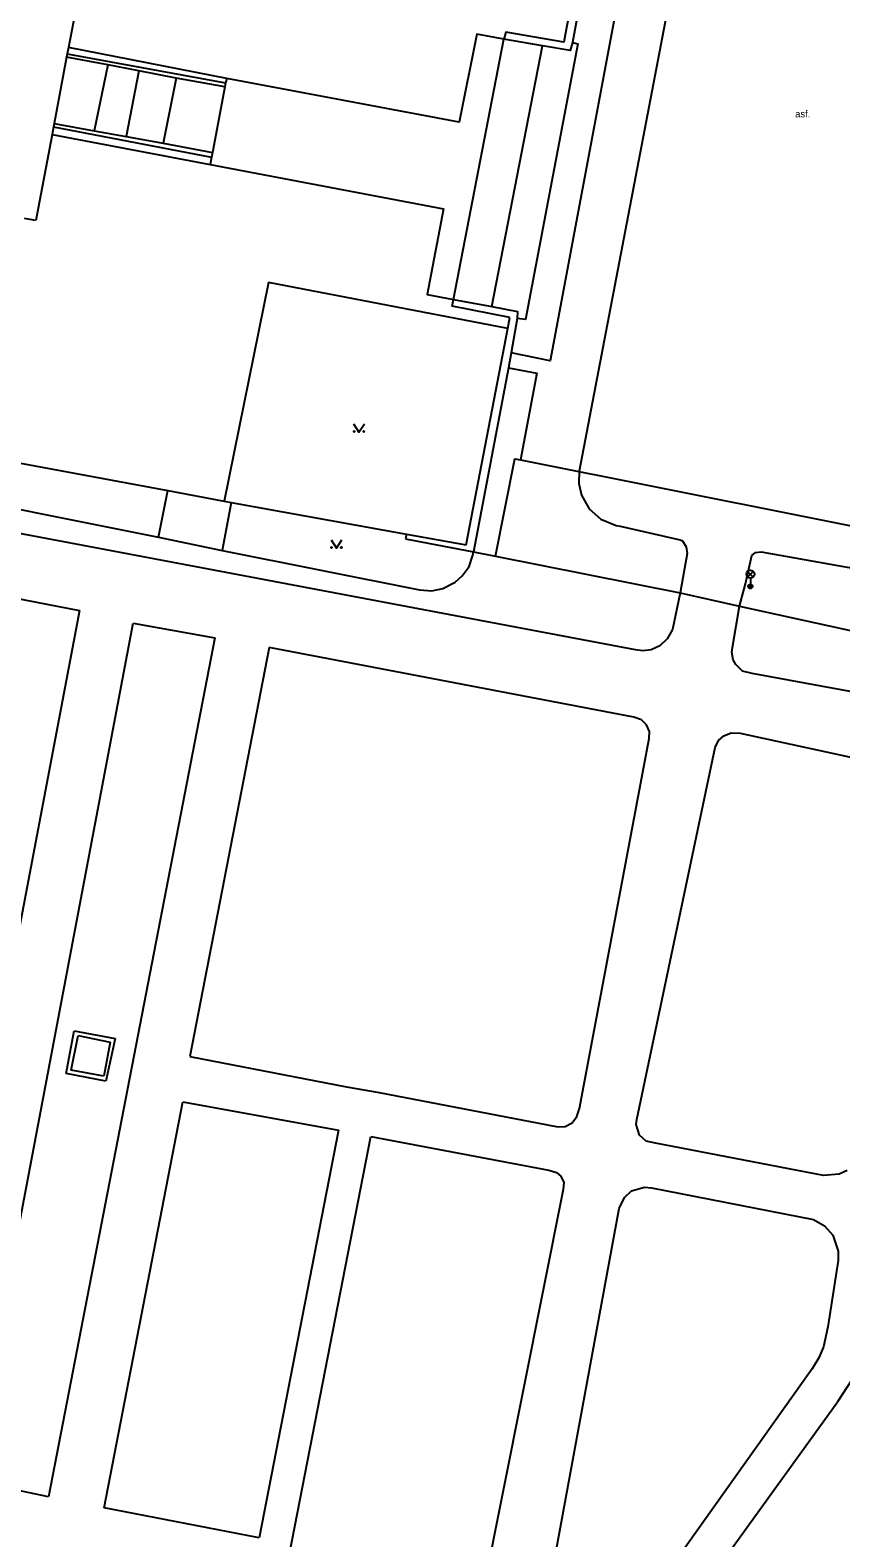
# Model space of a CAD drawing. Extents: x -599951 to -598963, y -1164095 to -1162939.
# Drawn here: x -599747.7 to -599672.6, y -1163262.9 to -1163123.5 of the extents above; entities that cross this region are included whole.
import ezdxf

# ---------------------------------------------------------------- set-up
doc = ezdxf.new("R2010")
doc.units = 0
for name, color, linetype in [('Level 11', 7, 'Continuous'), ('Level 33', 7, 'Continuous'), ('Level 36', 7, 'Continuous'), ('Level 40', 7, 'Continuous'), ('Level 5', 7, 'Continuous'), ('Level 51', 7, 'Continuous'), ('Level 54', 7, 'Continuous'), ('Level 7', 7, 'Continuous')]:
    doc.layers.add(name, color=color, linetype=linetype)

msp = doc.modelspace()

# ---------------------------------------------------------------- linework, layer by layer
at = {"layer": 'Level 11'}
for points in [[(-599696.89, -1163121.58), (-599693.53, -1163122.18), (-599699.52, -1163154.07), (-599703.13, -1163153.32)], [(-599696.89, -1163121.58), (-599697.45, -1163124.63)], [(-599688.59, -1163121.25), (-599696.84, -1163164.28), (-599696.87, -1163165.42), (-599696.63, -1163166.48), (-599695.9, -1163167.77), (-599694.82, -1163168.72), (-599693.41, -1163169.3), (-599693.03, -1163169.37), (-599687.5, -1163170.62), (-599687.29, -1163170.72), (-599686.93, -1163171.27), (-599686.85, -1163171.88), (-599687.49, -1163175.53)], [(-599703.81, -1163124.32), (-599706.3, -1163123.86), (-599707.93, -1163131.98), (-599729.45, -1163127.95)], [(-599729.45, -1163127.95), (-599744.1, -1163125.09)], [(-599708.47, -1163148.38), (-599703.81, -1163124.32)], [(-599704.92, -1163149.04), (-599700.24, -1163124.94)], [(-599700.24, -1163124.94), (-599703.81, -1163124.32)], [(-599697.45, -1163124.63), (-599696.97, -1163124.74), (-599701.82, -1163150.24), (-599702.57, -1163150.15)], [(-599697.45, -1163124.63), (-599697.66, -1163125.36), (-599700.24, -1163124.94)], [(-599740.47, -1163126.68), (-599744.27, -1163125.96)], [(-599744.21, -1163125.66), (-599729.57, -1163128.35)], [(-599740.47, -1163126.68), (-599741.71, -1163132.78)], [(-599737.6, -1163127.25), (-599740.47, -1163126.68)], [(-599737.6, -1163127.25), (-599738.77, -1163133.32)], [(-599734.15, -1163127.91), (-599737.6, -1163127.25)], [(-599734.15, -1163127.91), (-599735.35, -1163133.94)], [(-599729.63, -1163128.71), (-599734.15, -1163127.91)], [(-599729.45, -1163127.95), (-599729.57, -1163128.35)], [(-599729.63, -1163128.71), (-599730.77, -1163134.78)], [(-599729.57, -1163128.35), (-599729.63, -1163128.71)], [(-599745.43, -1163132.1), (-599741.71, -1163132.78)], [(-599745.62, -1163133.12), (-599730.98, -1163135.9)], [(-599745.49, -1163132.42), (-599730.88, -1163135.21)], [(-599741.71, -1163132.78), (-599738.77, -1163133.32)], [(-599738.77, -1163133.32), (-599735.35, -1163133.94)], [(-599735.35, -1163133.94), (-599730.77, -1163134.78)], [(-599730.77, -1163134.78), (-599730.88, -1163135.21)], [(-599730.88, -1163135.21), (-599730.98, -1163135.9)], [(-599730.98, -1163135.9), (-599709.38, -1163140.01), (-599710.91, -1163147.93), (-599708.47, -1163148.38)], [(-599703.44, -1163151.07), (-599725.58, -1163146.81), (-599729.7, -1163167.04)], [(-599708.47, -1163148.38), (-599704.92, -1163149.04)], [(-599704.92, -1163149.04), (-599702.55, -1163149.51), (-599702.57, -1163150.15)], [(-599702.57, -1163150.15), (-599703.13, -1163153.32)], [(-599703.13, -1163153.32), (-599703.39, -1163154.72), (-599706.61, -1163171.72)], [(-599703.39, -1163154.72), (-599700.76, -1163155.21), (-599702.28, -1163163.23)], [(-599704.59, -1163172.12), (-599702.8, -1163163.12), (-599702.28, -1163163.23), (-599662.06, -1163171.24), (-599664.14, -1163180.68)], [(-599681.44, -1163174.69), (-599680.87, -1163172.08), (-599680.51, -1163171.78), (-599680.01, -1163171.72), (-599667.53, -1163173.95), (-599667.04, -1163173.81), (-599666.62, -1163173.48), (-599666.39, -1163172.98), (-599665.48, -1163168.29)], [(-599706.61, -1163171.72), (-599704.59, -1163172.12), (-599687.49, -1163175.53)], [(-599687.49, -1163175.53), (-599681.99, -1163176.75)], [(-599681.99, -1163176.75), (-599681.44, -1163174.69)]]:
    msp.add_lwpolyline(points, dxfattribs=at)
at = {"layer": 'Level 33'}
for p, q in [((-599681.25, -1163174.07), (-599680.72, -1163173.54)), ((-599681.25, -1163173.54), (-599680.72, -1163174.07)), ((-599680.99, -1163174.18), (-599680.99, -1163174.93))]:
    msp.add_line(p, q, dxfattribs=at)
for centre, radius in [((-599680.99, -1163173.8), 0.375), ((-599680.99, -1163174.93), 0.2), ((-599680.99, -1163174.93), 0.145), ((-599680.99, -1163174.93), 0.0876)]:
    msp.add_circle(centre, radius, dxfattribs=at)
at = {"layer": 'Level 36'}
for points in [[(-599717.72, -1163159.9), (-599717.22, -1163160.65), (-599716.72, -1163159.9)], [(-599719.8, -1163170.63), (-599719.3, -1163171.38), (-599718.8, -1163170.63)]]:
    msp.add_lwpolyline(points, dxfattribs=at)
for centre in [(-599717.67, -1163160.6), (-599716.77, -1163160.6), (-599719.75, -1163171.33), (-599718.85, -1163171.33)]:
    msp.add_circle(centre, 0.05, dxfattribs=at)
at = {"layer": 'Level 5'}
for points in [[(-599742.51, -1163116.7), (-599744.1, -1163125.09)], [(-599744.1, -1163125.09), (-599744.21, -1163125.66)], [(-599744.27, -1163125.96), (-599745.43, -1163132.1)], [(-599744.21, -1163125.66), (-599744.27, -1163125.96)], [(-599745.43, -1163132.1), (-599745.49, -1163132.42)], [(-599745.62, -1163133.12), (-599747.13, -1163141.09)], [(-599745.49, -1163132.42), (-599745.62, -1163133.12)], [(-599747.13, -1163141.09), (-599748.17, -1163140.89)]]:
    msp.add_lwpolyline(points, dxfattribs=at)
at = {"layer": 'Level 51'}
for points in [[(-599752.41, -1163162.81), (-599734.92, -1163166.06)], [(-599734.92, -1163166.06), (-599729.7, -1163167.04), (-599729.03, -1163167.16)], [(-599729.03, -1163167.16), (-599712.82, -1163170.11)], [(-599712.82, -1163170.11), (-599712.9, -1163170.52)], [(-599712.9, -1163170.52), (-599706.61, -1163171.72)]]:
    msp.add_lwpolyline(points, dxfattribs=at)
at = {"layer": 'Level 54'}
for points in [[(-599708.59, -1163149.01), (-599708.47, -1163148.38)], [(-599703.25, -1163150.07), (-599708.59, -1163149.01)], [(-599707.29, -1163171.1), (-599703.44, -1163151.07), (-599703.25, -1163150.07)], [(-599782.49, -1163161.03), (-599735.77, -1163170.38)], [(-599691.63, -1163180.81), (-599782.95, -1163163.56)], [(-599735.77, -1163170.38), (-599734.92, -1163166.06)], [(-599729.03, -1163167.16), (-599729.87, -1163171.61)], [(-599735.77, -1163170.38), (-599729.87, -1163171.61)], [(-599712.82, -1163170.11), (-599707.29, -1163171.1)], [(-599729.87, -1163171.61), (-599711.62, -1163175.26)], [(-599707.03, -1163173.08), (-599706.67, -1163172.05)], [(-599706.67, -1163172.05), (-599706.61, -1163171.72)], [(-599761.11, -1163173.67), (-599743.08, -1163177.17)], [(-599708.32, -1163174.55), (-599707.66, -1163173.96)], [(-599707.66, -1163173.96), (-599707.03, -1163173.08)], [(-599711.62, -1163175.26), (-599710.46, -1163175.34)], [(-599710.46, -1163175.34), (-599709.47, -1163175.13)], [(-599709.47, -1163175.13), (-599708.32, -1163174.55)], [(-599687.49, -1163175.53), (-599688.19, -1163178.91)], [(-599682.65, -1163180.57), (-599681.99, -1163176.75)], [(-599743.08, -1163177.17), (-599758.23, -1163256.83)], [(-599753.18, -1163257.65), (-599738.11, -1163178.34)], [(-599738.11, -1163178.34), (-599730.57, -1163179.68)], [(-599730.57, -1163179.68), (-599745.94, -1163259.16)], [(-599688.68, -1163179.77), (-599689.37, -1163180.43)], [(-599688.19, -1163178.91), (-599688.68, -1163179.77)], [(-599725.54, -1163180.58), (-599732.88, -1163218.42)], [(-599691.79, -1163187.04), (-599725.54, -1163180.58)], [(-599690.94, -1163180.89), (-599691.63, -1163180.81)], [(-599690.16, -1163180.79), (-599690.94, -1163180.89)], [(-599689.37, -1163180.43), (-599690.16, -1163180.79)], [(-599682.7, -1163181.02), (-599682.65, -1163180.57)], [(-599682.59, -1163181.72), (-599682.7, -1163181.02)], [(-599682.34, -1163182.15), (-599682.59, -1163181.72)], [(-599681.71, -1163182.76), (-599682.34, -1163182.15)], [(-599680.82, -1163183), (-599681.71, -1163182.76)], [(-599657.97, -1163187.17), (-599680.82, -1163183)], [(-599691.07, -1163187.27), (-599691.79, -1163187.04)], [(-599690.6, -1163187.73), (-599691.07, -1163187.27)], [(-599690.34, -1163188.36), (-599690.6, -1163187.73)], [(-599696.8, -1163223.24), (-599690.37, -1163189.01)], [(-599690.37, -1163189.01), (-599690.34, -1163188.36)], [(-599684.24, -1163189.83), (-599683.94, -1163189.2)], [(-599683.94, -1163189.2), (-599683.44, -1163188.74)], [(-599683.44, -1163188.74), (-599682.76, -1163188.47)], [(-599682.76, -1163188.47), (-599681.93, -1163188.51)], [(-599681.93, -1163188.51), (-599665.31, -1163192.13)], [(-599691.5, -1163224.24), (-599684.24, -1163189.83)], [(-599744.32, -1163220), (-599743.56, -1163216.03)], [(-599743.56, -1163216.03), (-599739.77, -1163216.75)], [(-599743.85, -1163219.67), (-599743.2, -1163216.49)], [(-599743.2, -1163216.49), (-599740.25, -1163217.08)], [(-599740.25, -1163217.08), (-599740.83, -1163220.24)], [(-599739.77, -1163216.75), (-599740.63, -1163220.69)], [(-599732.88, -1163218.42), (-599718.37, -1163221.23)], [(-599740.63, -1163220.69), (-599744.32, -1163220)], [(-599740.83, -1163220.24), (-599743.85, -1163219.67)], [(-599718.37, -1163221.23), (-599715.35, -1163221.76)], [(-599740.79, -1163260.16), (-599733.53, -1163222.6)], [(-599733.53, -1163222.6), (-599719.11, -1163225.24)], [(-599715.35, -1163221.76), (-599698.96, -1163224.9)], [(-599697.49, -1163224.55), (-599697.04, -1163223.97)], [(-599697.04, -1163223.97), (-599696.8, -1163223.24)], [(-599691.57, -1163224.7), (-599691.5, -1163224.24)], [(-599719.11, -1163225.24), (-599726.45, -1163262.94)], [(-599698.96, -1163224.9), (-599698.74, -1163224.93)], [(-599698.74, -1163224.93), (-599698.14, -1163224.88)], [(-599698.14, -1163224.88), (-599697.49, -1163224.55)], [(-599691.27, -1163225.7), (-599691.57, -1163224.7)], [(-599690.63, -1163226.26), (-599691.27, -1163225.7)], [(-599723.61, -1163264.28), (-599716.13, -1163225.83)], [(-599716.13, -1163225.83), (-599699.64, -1163228.94)], [(-599689.78, -1163226.45), (-599690.63, -1163226.26)], [(-599674.24, -1163229.42), (-599689.78, -1163226.45)], [(-599699.64, -1163228.94), (-599698.93, -1163229.15)], [(-599698.93, -1163229.15), (-599698.52, -1163229.5)], [(-599698.52, -1163229.5), (-599698.26, -1163230.06)], [(-599672.78, -1163229.31), (-599674.24, -1163229.42)], [(-599672.04, -1163228.95), (-599672.78, -1163229.31)], [(-599698.32, -1163230.71), (-599705.76, -1163268)], [(-599698.26, -1163230.06), (-599698.32, -1163230.71)], [(-599692.65, -1163231.47), (-599691.99, -1163230.83)], [(-599691.99, -1163230.83), (-599690.8, -1163230.49)], [(-599690.8, -1163230.49), (-599690.13, -1163230.57)], [(-599690.13, -1163230.57), (-599675.16, -1163233.5)], [(-599699.71, -1163268.16), (-599693.13, -1163232.47)], [(-599693.13, -1163232.47), (-599692.65, -1163231.47)], [(-599675.16, -1163233.5), (-599674.13, -1163234.08)], [(-599674.13, -1163234.08), (-599673.35, -1163234.96)], [(-599673.35, -1163234.96), (-599672.86, -1163236.44)], [(-599672.86, -1163236.44), (-599672.88, -1163237.28)], [(-599672.88, -1163237.28), (-599673.83, -1163243.43)], [(-599673.83, -1163243.43), (-599674.24, -1163245.28)], [(-599674.24, -1163245.28), (-599674.67, -1163246.29)], [(-599674.67, -1163246.29), (-599675.29, -1163247.3)], [(-599675.29, -1163247.3), (-599690.37, -1163268.51)], [(-599672.89, -1163250.33), (-599671.52, -1163248.2)], [(-599687.6, -1163270.72), (-599672.89, -1163250.33)], [(-599745.94, -1163259.16), (-599753.18, -1163257.65)], [(-599726.45, -1163262.94), (-599740.79, -1163260.16)]]:
    msp.add_lwpolyline(points, dxfattribs=at)
at = {"layer": 'Level 7'}
for points in [[(-599739.36, -1163094.82), (-599716.47, -1163099.09), (-599694.04, -1163103.27), (-599697.97, -1163123.09), (-599698.27, -1163124.58), (-599703.63, -1163123.67), (-599703.81, -1163124.32)], [(-599681.99, -1163176.75), (-599664.14, -1163180.68), (-599661.12, -1163181.35), (-599658.67, -1163169.5)]]:
    msp.add_lwpolyline(points, dxfattribs=at)

# ---------------------------------------------------------------- texts
at = {"layer": 'Level 40'}
msp.add_text('asf.', height=0.65, dxfattribs=at).set_placement((-599676.85, -1163131.54))

doc.saveas('drawing.dxf')
